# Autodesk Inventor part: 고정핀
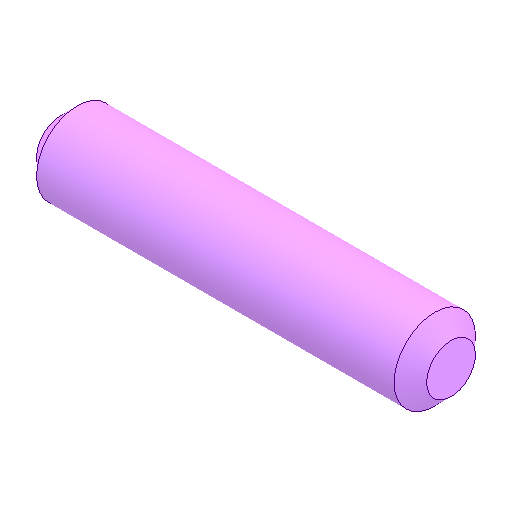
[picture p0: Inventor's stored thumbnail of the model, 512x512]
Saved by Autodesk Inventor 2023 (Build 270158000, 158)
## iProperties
Created: 2025-02
Part Number: 고정핀
Material: 강철, 탄소
Document SubType Name: Modeling
Designer: home
Density: 7.85 g/cm^3
Appearance: 기본값
Author: jhkim
Sending System: Autodesk Inventor 2025
Preprocessor: ST-DEVELOPER v20
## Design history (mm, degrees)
node "고정핀1"
node "솔리드2"
node "솔리드1"
